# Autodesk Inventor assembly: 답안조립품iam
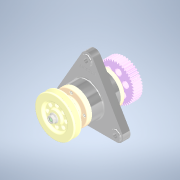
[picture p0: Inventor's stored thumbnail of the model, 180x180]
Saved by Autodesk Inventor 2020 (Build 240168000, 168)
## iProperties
Created: 2023-04
Part Number: 답안조립품iam
Document SubType Name: Assembly
Designer: home
Author: home
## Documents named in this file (11)
- C:\Users\home\Desktop\730407V1023\답안조립품iam.iam
- C:\Users\home\Desktop\730407V1023\묻힘키 5x5x16.ipt
- C:\Users\home\Desktop\730407V1023\베어링 6204.ipt
- C:\Users\home\Desktop\730407V1023\오일 실 20 32 8.ipt
- C:\Users\home\Desktop\730407V1023\커버.ipt
- C:\Users\home\Desktop\730407V1023\축.ipt
- C:\Users\home\Desktop\730407V1023\스퍼기어.ipt
- C:\Users\home\Desktop\730407V1023\볼트 M4 x 12.ipt
- C:\Users\home\Desktop\730407V1023\6각 플랜지 너트 M10.ipt
- C:\Users\home\Desktop\730407V1023\v-벨트풀리.ipt
- C:\Users\home\Desktop\730407V1023\본체.ipt
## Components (3 placed, 2 different names)
1. 6각 플랜지 너트 M10:1 — Mate:25, Mate:26
2. 6각 플랜지 너트 M10:2 — Mate:34, Mate:35
3. v-벨트풀리:1 — Mate:21, Mate:22, Mate:23, Mate:24, Mate:26
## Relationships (8: Mate 8)
- Mate:21: v-벨트풀리:1
- Mate:22: v-벨트풀리:1
- Mate:23: v-벨트풀리:1
- Mate:24: v-벨트풀리:1
- Mate:25: 6각 플랜지 너트 M10:1
- Mate:26: 6각 플랜지 너트 M10:1 ↔ v-벨트풀리:1
- Mate:34: 6각 플랜지 너트 M10:2
- Mate:35: 6각 플랜지 너트 M10:2
